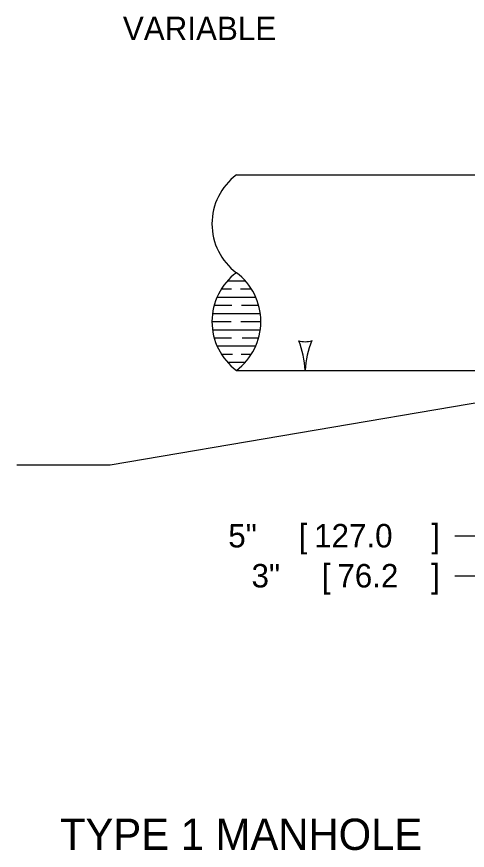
# Model space of a CAD drawing. Extents: x 49991.4 to 50028.3, y 49987.6 to 50011.4.
# Drawn here: x 50024.802 to 50025.956, y 49994.061 to 49996.194 of the extents above; entities that cross this region are included whole.
import ezdxf

# ---------------------------------------------------------------- set-up
doc = ezdxf.new("R2010")
doc.units = 0
for name, color, linetype in [('Level 1', 7, 'Continuous'), ('Level 2', 7, 'Continuous'), ('Level 3', 7, 'Continuous')]:
    doc.layers.add(name, color=color, linetype=linetype)

msp = doc.modelspace()

# ---------------------------------------------------------------- linework, layer by layer
at = {"layer": 'Level 1'}
for p, q in [((50025.3647, 49995.7888), (50026.2635, 49995.7888)), ((50025.3419, 49995.518), (50025.3873, 49995.518)), ((50025.3152, 49995.4763), (50025.4141, 49995.4763)), ((50025.3262, 49995.4971), (50025.3523, 49995.4971)), ((50025.3748, 49995.4971), (50025.4031, 49995.4971)), ((50025.3078, 49995.4554), (50025.3534, 49995.4554)), ((50025.378, 49995.4554), (50025.4215, 49995.4554)), ((50025.3035, 49995.4346), (50025.4257, 49995.4346)), ((50025.3021, 49995.4138), (50025.3513, 49995.4138)), ((50025.3759, 49995.4138), (50025.4271, 49995.4138)), ((50025.3035, 49995.393), (50025.4257, 49995.393)), ((50025.3078, 49995.3721), (50025.3523, 49995.3721)), ((50025.3791, 49995.3721), (50025.4215, 49995.3721)), ((50025.3152, 49995.3513), (50025.4141, 49995.3513)), ((50025.3262, 49995.3304), (50025.3545, 49995.3304)), ((50025.3769, 49995.3304), (50025.4031, 49995.3304)), ((50025.3419, 49995.3096), (50025.3873, 49995.3096)), ((50025.3647, 49995.2888), (50027.7638, 49995.2888))]:
    msp.add_line(p, q, dxfattribs=at)
for centre, start, end in [((50025.4584, 49995.6638), 126.8699, 233.1301), ((50025.4584, 49995.4138), 126.8699, 233.1301), ((50025.2709, 49995.4138), 306.8699, 53.1301)]:
    msp.add_arc(centre, 0.1563, start, end, dxfattribs=at)
at = {"layer": 'Level 3'}
for p, q in [((50025.0417, 49995.0471), (50026.0968, 49995.2263)), ((50024.8023, 49995.0471), (50025.0417, 49995.0471)), ((50025.9234, 49994.8659), (50026.1593, 49994.8659)), ((50025.9234, 49994.7635), (50026.0968, 49994.7635))]:
    msp.add_line(p, q, dxfattribs=at)
for centre, radius, start, end in [((50025.5409, 49995.417), 0.0548, 252.1388, 287.8612), ((50025.3082, 49995.2773), 0.233, 2.8273, 22.0772), ((50025.763, 49995.2797), 0.2223, 157.456, 177.6395)]:
    msp.add_arc(centre, radius, start, end, dxfattribs=at)

# ---------------------------------------------------------------- texts
at = {"layer": 'Level 2'}
for s, height, p in [('VARIABLE', 0.06, (50025.0741, 49996.1338)), ('5" ', 0.06, (50025.3439, 49994.8359)), ('[', 0.06, (50025.5239, 49994.8359)), ('127.0', 0.06, (50025.5636, 49994.8359)), (']', 0.06, (50025.8636, 49994.8359)), ('3" ', 0.06, (50025.4034, 49994.7335)), ('[', 0.06, (50025.5834, 49994.7335)), ('76.2', 0.06, (50025.6231, 49994.7335)), (']', 0.06, (50025.8631, 49994.7335)), ('TYPE 1 MANHOLE', 0.08, (50024.913, 49994.062))]:
    msp.add_text(s, height=height, dxfattribs=at).set_placement(p)

doc.saveas('drawing.dxf')
